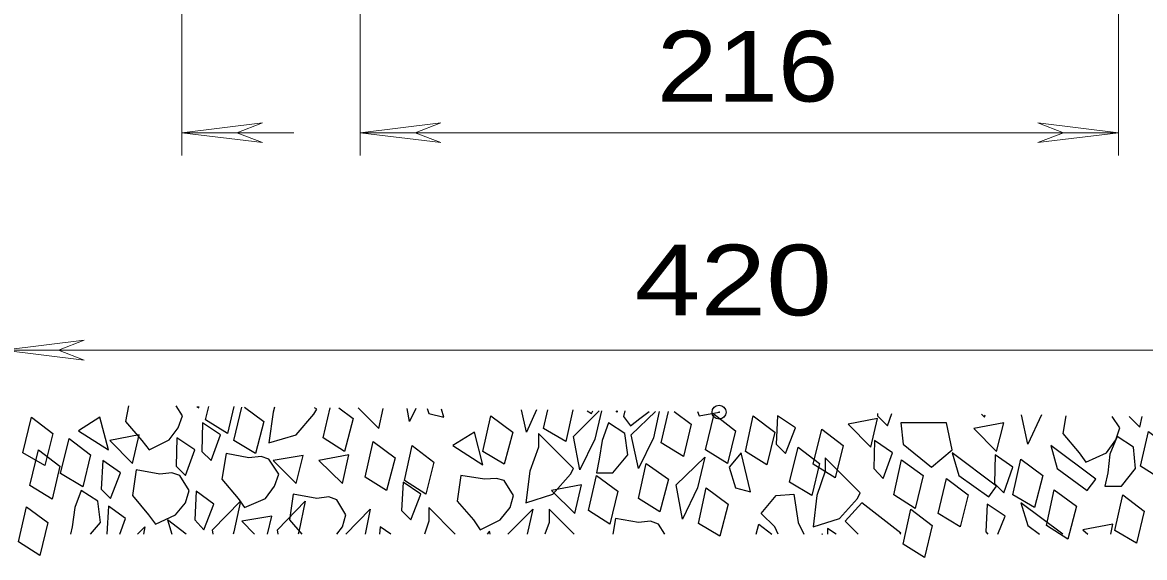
# Model space of a CAD drawing. Extents: x 312583 to 312854, y 144419 to 144597.
# Drawn here: x 312703.67 to 312715.73, y 144443.4 to 144449.15 of the extents above; entities that cross this region are included whole.
import ezdxf

# ---------------------------------------------------------------- set-up
doc = ezdxf.new("R2010")
doc.units = 0
doc.header["$LTSCALE"] = 0.3
doc.header["$PDMODE"] = 32
doc.header["$PDSIZE"] = 0.15
doc.layers.add('1', color=7, linetype='Continuous', lineweight=25)
doc.layers.add('2', color=7, linetype='Continuous', lineweight=13)

msp = doc.modelspace()

# ---------------------------------------------------------------- linework, layer by layer
at = {"layer": '1'}
for p, q in [((312705.6337, 144444.8764), (312705.672, 144445.022)), ((312705.9404, 144444.654), (312706.0247, 144445.0144)), ((312706.8987, 144444.6847), (312706.9754, 144445.0067)), ((312709.2677, 144444.7844), (312709.3137, 144444.9837)), ((312709.5897, 144444.7), (312709.8657, 144444.976)), ((312710.2107, 144444.7154), (312710.4714, 144444.9684)), ((312710.5327, 144444.631), (312710.6094, 144444.9684)), ((312704.591, 144443.9487), (312704.5757, 144443.6497)), ((312706.0247, 144443.7877), (312706.1627, 144443.6497)), ((312708.0334, 144443.7877), (312707.9874, 144443.6497)), ((312709.329, 144443.7724), (312709.283, 144443.6497)), ((312714.4734, 144443.7417), (312714.596, 144443.6497)), ((312705.718, 144443.6497), (312705.7104, 144443.6957)), ((312706.4157, 144443.6497), (312706.408, 144443.6957)), ((312707.512, 144443.7264), (312707.5044, 144443.6497)), ((312707.627, 144443.6497), (312707.512, 144443.7264)), ((312712.319, 144443.711), (312712.319, 144443.6497)), ((312712.411, 144443.6497), (312712.319, 144443.711)), ((312715.0637, 144443.6957), (312715.1174, 144443.6497))]:
    msp.add_line(p, q, dxfattribs=at)
for points in [[(312704.8057, 144445.0297), (312704.775, 144444.861), (312704.9514, 144444.654)], [(312704.9514, 144444.654), (312705.028, 144444.5544), (312705.2427, 144444.6617), (312705.3424, 144444.792), (312705.3884, 144444.9224), (312705.3194, 144445.0297)], [(312705.5417, 144445.022), (312705.5647, 144445.0067), (312705.5647, 144445.022)], [(312705.9404, 144445.022), (312705.8714, 144444.7307), (312705.6337, 144444.8764)], [(312706.0554, 144445.0144), (312706.2624, 144444.861), (312706.1704, 144444.516), (312705.9404, 144444.654)], [(312706.3774, 144445.0144), (312706.362, 144444.9607), (312706.316, 144444.631), (312706.6074, 144444.7154), (312706.799, 144444.9377), (312706.8297, 144444.9914), (312706.8067, 144445.0067)], [(312707.0674, 144445.0067), (312707.2207, 144444.8917), (312707.1287, 144444.539), (312706.8987, 144444.6847)], [(312707.2744, 144445.0067), (312707.4967, 144444.7844), (312707.5427, 144444.999)], [(312707.8954, 144444.999), (312707.8264, 144444.861), (312707.8034, 144444.999)], [(312708.018, 144444.999), (312708.0334, 144444.9454), (312708.1944, 144444.907), (312708.1714, 144444.9914)], [(312709.191, 144444.9837), (312709.0837, 144444.746), (312709.03, 144444.9837)], [(312709.582, 144444.9837), (312709.5054, 144444.6464), (312709.2677, 144444.7844)], [(312709.8887, 144444.976), (312709.8197, 144444.6694), (312709.6587, 144444.3397), (312709.5897, 144444.7)], [(312709.7354, 144444.976), (312709.7814, 144444.9454), (312709.7967, 144444.976)], [(312710.0574, 144444.976), (312710.0574, 144444.9607), (312710.0497, 144444.976)], [(312710.1417, 144444.976), (312710.1264, 144444.9147), (312710.203, 144444.815), (312710.3027, 144444.8917), (312710.4024, 144444.9684)], [(312710.5097, 144444.9684), (312710.4484, 144444.6847), (312710.2874, 144444.355), (312710.2107, 144444.7154)], [(312710.6707, 144444.9684), (312710.8547, 144444.8304), (312710.7704, 144444.4854), (312710.5327, 144444.631)], [(312710.9237, 144444.9684), (312710.939, 144444.9224), (312711.1537, 144444.9607)], [(312712.8557, 144444.9454), (312712.8557, 144444.9224), (312712.963, 144444.815), (312713.009, 144444.9454)], [(312713.975, 144444.9377), (312714.0057, 144444.907), (312714.0134, 144444.93)], [(312714.619, 144444.93), (312714.4734, 144444.6157), (312714.4044, 144444.93)], [(312714.8797, 144444.9224), (312714.849, 144444.7307), (312715.0254, 144444.5237)], [(312715.0254, 144444.5237), (312715.0944, 144444.424), (312715.3167, 144444.5237), (312715.4164, 144444.6617), (312715.4624, 144444.792), (312715.378, 144444.9147)], [(312715.562, 144444.9147), (312715.677, 144444.7997), (312715.7, 144444.9147)], [(312704.2997, 144444.1174), (312704.2307, 144443.9334), (312704.2, 144443.7264), (312704.1847, 144443.6497)], [(312704.3994, 144443.6497), (312704.5067, 144443.7724), (312704.476, 144444.0024), (312704.2997, 144444.1174)], [(312705.7104, 144443.6957), (312706.0094, 144444.0024), (312705.9404, 144443.6727), (312705.9327, 144443.6497)], [(312706.408, 144443.6957), (312706.707, 144444.0024), (312706.638, 144443.6727), (312706.6304, 144443.6497)], [(312707.0444, 144443.6497), (312707.1057, 144443.7264), (312707.144, 144443.8567), (312707.0444, 144444.0177), (312706.96, 144444.0484), (312706.8297, 144444.033), (312706.5767, 144444.079), (312706.5384, 144443.803), (312706.6687, 144443.6497)], [(312711.79, 144443.6497), (312711.7517, 144443.7264), (312711.606, 144443.872), (312711.767, 144444.0637), (312711.9587, 144444.079), (312712.0047, 144443.7724), (312712.066, 144443.6497)], [(312712.687, 144443.987), (312712.5107, 144443.7877), (312712.6487, 144443.6497)], [(312713.101, 144443.6497), (312713.1087, 144443.6574), (312712.687, 144443.987)], [(312714.849, 144443.6497), (312714.3967, 144443.987), (312714.4734, 144443.7417)], [(312704.7137, 144443.6497), (312704.775, 144443.8184), (312704.591, 144443.9487)], [(312707.144, 144443.6497), (312707.4047, 144443.918), (312707.351, 144443.6497)], [(312708.317, 144443.6497), (312708.0334, 144443.9334), (312708.0334, 144443.7877)], [(312708.8844, 144443.6497), (312709.1527, 144443.918), (312709.0914, 144443.6497)], [(312709.5974, 144443.6497), (312709.329, 144443.918), (312709.329, 144443.7724)], [(312714.0364, 144443.9717), (312714.021, 144443.6727), (312714.044, 144443.6497)], [(312714.1514, 144443.6497), (312714.228, 144443.8414), (312714.0364, 144443.9717)], [(312705.4267, 144443.6497), (312705.2274, 144443.803), (312705.2734, 144443.6497)], [(312706.3007, 144443.6497), (312706.3467, 144443.8414), (312706.0247, 144443.7877)], [(312710.571, 144443.6497), (312710.502, 144443.757), (312710.4177, 144443.7877), (312710.2874, 144443.7724), (312710.042, 144443.8184), (312710.0114, 144443.6497)], [(312711.5524, 144443.6497), (312711.583, 144443.757), (312711.721, 144443.6497)], [(312715.3627, 144443.6497), (312715.3857, 144443.757), (312715.0637, 144443.6957)], [(312704.9054, 144443.6497), (312704.982, 144443.7264), (312704.9667, 144443.6497)], [(312708.6927, 144443.6497), (312708.685, 144443.6804), (312708.662, 144443.6497)], [(312712.2577, 144443.6497), (312712.2654, 144443.6497), (312712.2577, 144443.6497)]]:
    msp.add_lwpolyline(points, dxfattribs=at)
for points in [[(312703.671, 144444.5237), (312703.763, 144444.907), (312703.993, 144444.7307), (312703.9087, 144444.3857)], [(312704.269, 144444.7614), (312704.591, 144444.5544), (312704.499, 144444.907)], [(312705.603, 144444.8457), (312705.5954, 144444.539), (312705.695, 144444.4394), (312705.7947, 144444.7154)], [(312708.616, 144444.539), (312708.7004, 144444.9224), (312708.938, 144444.746), (312708.846, 144444.401)], [(312709.9654, 144444.8457), (312709.8964, 144444.654), (312709.8657, 144444.4547), (312709.835, 144444.309), (312710.0114, 144444.309), (312710.1724, 144444.5007), (312710.1417, 144444.7307)], [(312711.008, 144444.5544), (312711.1, 144444.9377), (312711.33, 144444.7614), (312711.2457, 144444.4087)], [(312711.4374, 144444.539), (312711.5217, 144444.9224), (312711.7517, 144444.746), (312711.6674, 144444.3934)], [(312711.7824, 144444.9224), (312711.767, 144444.6157), (312711.8667, 144444.516), (312711.974, 144444.792)], [(312712.5414, 144444.8304), (312712.7867, 144444.585), (312712.8557, 144444.8917)], [(312713.1317, 144444.6157), (312713.4384, 144444.3704), (312713.6607, 144444.5544), (312713.5994, 144444.8457), (312713.1087, 144444.8457)], [(312713.8907, 144444.7844), (312714.136, 144444.539), (312714.2127, 144444.8457)], [(312704.6064, 144444.654), (312704.8517, 144444.4087), (312704.9207, 144444.7154)], [(312708.294, 144444.6004), (312708.616, 144444.3934), (312708.524, 144444.746)], [(312709.214, 144444.585), (312709.122, 144444.3244), (312709.076, 144443.987), (312709.3674, 144444.079), (312709.559, 144444.2937), (312709.5897, 144444.355), (312709.214, 144444.7307)], [(312712.1657, 144444.401), (312712.2577, 144444.7767), (312712.4877, 144444.6004), (312712.4034, 144444.2554)], [(312715.4317, 144444.7), (312715.355, 144444.5084), (312715.332, 144444.309), (312715.3014, 144444.1634), (312715.4777, 144444.1634), (312715.631, 144444.355), (312715.608, 144444.585)], [(312715.6847, 144444.378), (312715.769, 144444.7537), (312716.0067, 144444.5774), (312715.9147, 144444.2324)], [(312704.0774, 144444.3014), (312704.1694, 144444.677), (312704.3994, 144444.5007), (312704.315, 144444.1557)], [(312705.327, 144444.6847), (312705.3194, 144444.378), (312705.419, 144444.2784), (312705.5187, 144444.5544)], [(312707.351, 144444.263), (312707.4354, 144444.6464), (312707.673, 144444.47), (312707.581, 144444.1174)], [(312707.7727, 144444.2247), (312707.857, 144444.6004), (312708.087, 144444.424), (312708.0027, 144444.079)], [(312711.9127, 144444.2094), (312712.0047, 144444.585), (312712.2347, 144444.4087), (312712.1504, 144444.0637)], [(312712.825, 144444.654), (312712.8174, 144444.355), (312712.917, 144444.2477), (312713.0167, 144444.5237)], [(312714.7877, 144444.355), (312715.1097, 144444.1174), (312715.2017, 144444.24), (312714.7187, 144444.6004)], [(312703.7477, 144444.171), (312703.8397, 144444.5544), (312704.0697, 144444.378), (312703.9854, 144444.0254)], [(312705.9864, 144444.033), (312706.0554, 144443.9334), (312706.2777, 144444.033), (312706.3774, 144444.1634), (312706.4234, 144444.2937), (312706.316, 144444.4547), (312706.2317, 144444.4854), (312706.1014, 144444.47), (312705.856, 144444.516), (312705.81, 144444.24)], [(312706.362, 144444.4394), (312706.6074, 144444.194), (312706.684, 144444.493)], [(312706.8527, 144444.4394), (312707.1057, 144444.194), (312707.1747, 144444.5007)], [(312710.6937, 144444.1787), (312711.0004, 144444.4777), (312710.9237, 144444.148), (312710.7627, 144443.8107)], [(312711.261, 144444.3704), (312711.33, 144444.148), (312711.491, 144444.102), (312711.3914, 144444.5237)], [(312712.296, 144444.3244), (312712.204, 144444.0637), (312712.1657, 144443.7264), (312712.4494, 144443.8184), (312712.641, 144444.033), (312712.6717, 144444.0944), (312712.296, 144444.47)], [(312713.7297, 144444.2784), (312714.0517, 144444.0484), (312714.136, 144444.1634), (312713.6607, 144444.5237)], [(312714.1207, 144444.5007), (312714.113, 144444.194), (312714.2127, 144444.0944), (312714.3124, 144444.3704)], [(312704.5297, 144444.4394), (312704.5144, 144444.1327), (312704.614, 144444.033), (312704.7214, 144444.309)], [(312705.0204, 144443.8567), (312705.097, 144443.757), (312705.3117, 144443.8567), (312705.419, 144443.987), (312705.4574, 144444.1174), (312705.3577, 144444.2784), (312705.2734, 144444.309), (312705.143, 144444.2937), (312704.89, 144444.3397), (312704.8517, 144444.0637)], [(312710.2874, 144444.033), (312710.3717, 144444.4087), (312710.6094, 144444.24), (312710.5174, 144443.8874)], [(312713.032, 144444.0714), (312713.1164, 144444.447), (312713.3464, 144444.2784), (312713.262, 144443.9257)], [(312714.3124, 144444.0714), (312714.3967, 144444.4547), (312714.6344, 144444.2784), (312714.5424, 144443.9334)], [(312708.5164, 144443.803), (312708.5854, 144443.6957), (312708.8, 144443.803), (312708.9074, 144443.9334), (312708.9457, 144444.0637), (312708.846, 144444.2247), (312708.7617, 144444.2477), (312708.6314, 144444.24), (312708.3784, 144444.2784), (312708.34, 144444.0024)], [(312709.7507, 144443.9027), (312709.835, 144444.2784), (312710.065, 144444.1097), (312709.9807, 144443.757)], [(312713.5074, 144443.872), (312713.5994, 144444.2477), (312713.8294, 144444.0714), (312713.745, 144443.7264)], [(312705.534, 144444.1097), (312705.5187, 144443.803), (312705.6184, 144443.6957), (312705.7257, 144443.9717)], [(312707.7574, 144444.2094), (312707.742, 144443.9027), (312707.8417, 144443.803), (312707.949, 144444.079)], [(312709.352, 144444.1174), (312709.605, 144443.872), (312709.674, 144444.1787)], [(312710.9314, 144443.7647), (312711.0157, 144444.148), (312711.2534, 144443.9717), (312711.1614, 144443.6267)], [(312714.6727, 144443.7417), (312714.757, 144444.125), (312714.9947, 144443.9487), (312714.9027, 144443.596)], [(312715.4087, 144443.688), (312715.493, 144444.0714), (312715.723, 144443.895), (312715.6387, 144443.55)], [(312703.625, 144443.5654), (312703.7094, 144443.941), (312703.9394, 144443.7724), (312703.855, 144443.4197)], [(312713.1317, 144443.5424), (312713.216, 144443.918), (312713.446, 144443.7417), (312713.3617, 144443.3967)]]:
    msp.add_lwpolyline(points, close=True, dxfattribs=at)
msp.add_point((312711.1537, 144444.9607), dxfattribs=at)
at = {"layer": '2'}
for p, q in [((312707.2974, 144451.1477), (312707.2974, 144447.7207)), ((312715.447, 144451.1477), (312715.447, 144447.7207)), ((312705.3807, 144449.7677), (312705.3807, 144447.7207)), ((312705.3807, 144447.966), (312706.247, 144448.0734)), ((312706.5844, 144447.966), (312705.3807, 144447.966)), ((312705.3807, 144447.966), (312706.247, 144447.8587)), ((312706.247, 144448.0734), (312705.971, 144447.966)), ((312706.247, 144447.8587), (312705.971, 144447.966)), ((312707.2974, 144447.966), (312708.1637, 144448.0734)), ((312707.2974, 144447.966), (312715.447, 144447.966)), ((312707.2974, 144447.966), (312708.1637, 144447.8587)), ((312708.1637, 144448.0734), (312707.8877, 144447.966)), ((312708.1637, 144447.8587), (312707.8877, 144447.966)), ((312714.5807, 144448.0734), (312714.8567, 144447.966)), ((312715.447, 144447.966), (312714.5807, 144448.0734)), ((312714.5807, 144447.8587), (312714.8567, 144447.966)), ((312715.447, 144447.966), (312714.5807, 144447.8587)), ((312703.464, 144445.6277), (312704.3304, 144445.735)), ((312704.3304, 144445.735), (312704.0544, 144445.6277)), ((312703.464, 144445.6277), (312719.2804, 144445.6277)), ((312703.464, 144445.6277), (312704.3304, 144445.5204)), ((312704.3304, 144445.5204), (312704.0544, 144445.6277))]:
    msp.add_line(p, q, dxfattribs=at)

# ---------------------------------------------------------------- texts
for s, width, p in [('216 ', 1.15, (312710.4864, 144448.301)), ('420 ', 1.25, (312710.247, 144446.0015))]:
    msp.add_text(s, height=0.76, dxfattribs=dict(at, width=width)).set_placement(p)

doc.saveas('drawing.dxf')
